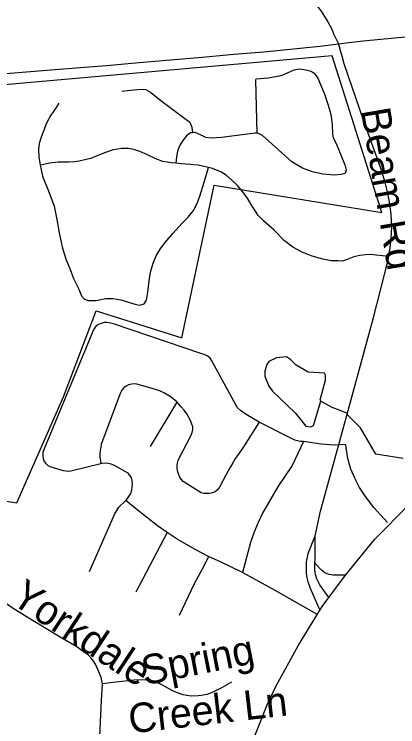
# Model space of a CAD drawing. Extents: x 1383679 to 1536984, y 460658 to 651027.
# Drawn here: x 1424801 to 1426040, y 517873 to 520172 of the extents above; entities that cross this region are included whole.
import ezdxf

# ---------------------------------------------------------------- set-up
doc = ezdxf.new("R2010")
doc.units = 0
for name, color, linetype in [('Default', 7, 'Continuous'), ('Exist Boundary Political City Limit New', 7, 'Continuous'), ('Exist Hydrographic Misc Water Feature', 7, 'Continuous'), ('Exist Road Non-System Type 51', 7, 'Continuous'), ('Exist Road Non-System Type 51 Label', 7, 'Continuous'), ('Exist Road Primary NC UnDivided 4 Lane Attributed', 7, 'Continuous'), ('Exist Road Secondary Type 51 Attributed', 7, 'Continuous'), ('Map Preparation Boundary City Limit Buffer Line', 7, 'Continuous')]:
    doc.layers.add(name, color=color, linetype=linetype)

msp = doc.modelspace()

# ---------------------------------------------------------------- linework, layer by layer
at = {"layer": 'Default'}
msp.add_lwpolyline([(1422823.6, 517723.8), (1422904, 517956.5), (1422867.1, 518120.3), (1422785.2, 518338.7), (1422874.1, 518503.7), (1422925.1, 518771.5), (1423065.2, 518770.9), (1423478.6, 518764.2), (1423776.6, 518761.8), (1424809.6, 518595.3), (1424959.4, 518937.5), (1425065.6, 519215.2), (1425341.9, 519127.2), (1425446.9, 519620.5), (1425988, 519531.9), (1425828.1, 520037.6), (1424757.9, 519942.8), (1424674.9, 520412.2), (1424293.4, 521236.2), (1424534, 521348.2), (1424715.6, 521432.8), (1424890.4, 521491.6), (1424961, 521509.3), (1424693.6, 522254.9)], dxfattribs=at)
at = {"layer": 'Exist Boundary Political City Limit New'}
msp.add_lwpolyline([(1422823.6, 517723.8), (1422904, 517956.5), (1422867.1, 518120.3), (1422785.2, 518338.7), (1422874.1, 518503.7), (1422925.1, 518771.5), (1423065.2, 518770.9), (1423478.6, 518764.2), (1423776.6, 518761.8), (1424809.6, 518595.3), (1424959.4, 518937.5), (1425065.6, 519215.2), (1425341.9, 519127.2), (1425446.9, 519620.5), (1425988, 519531.9), (1425828.1, 520037.6), (1424757.9, 519942.8), (1424674.9, 520412.2), (1424293.4, 521236.2), (1424534, 521348.2), (1424715.6, 521432.8), (1424890.4, 521491.6), (1424961, 521509.3), (1424693.6, 522254.9)], dxfattribs=at)
at = {"layer": 'Exist Hydrographic Misc Water Feature'}
for points in [[(1425790.7, 518922.8), (1425788.7, 518927.9), (1425806.1, 518991.5), (1425806.4, 519007.5), (1425802.6, 519013.6), (1425750.6, 519016.7), (1425711.1, 519039.6), (1425693.5, 519058), (1425679.7, 519066.3), (1425647.6, 519063), (1425623.4, 519051.6), (1425617.1, 519041.7), (1425610.7, 519019.9), (1425610.3, 519003.9), (1425623.6, 518971.6), (1425635.3, 518955.3), (1425707.8, 518885.7), (1425742.8, 518843), (1425758.8, 518840.6), (1425766.9, 518844.4), (1425790.7, 518922.8)], [(1426056.7, 518738), (1425968.9, 518751.9), (1425919.4, 518837.3), (1425877.4, 518878.6), (1425875.8, 518884), (1425828.1, 518903.1), (1425790.7, 518922.8)]]:
    msp.add_lwpolyline(points, dxfattribs=at)
at = {"layer": 'Exist Road Non-System Type 51'}
for p, q in [((1425240.9, 518776.6), (1425326.8, 518919.8)), ((1425294.2, 518499.1), (1425194, 518306.8))]:
    msp.add_line(p, q, dxfattribs=at)
for points in [[(1425772.6, 518488.7), (1425790.2, 518568), (1425876, 518881.1), (1425960.6, 519189.2), (1426008.3, 519378.3), (1426014.6, 519419.1), (1426018.3, 519448.3), (1426020.2, 519486.4), (1426018.4, 519526.8), (1426012.5, 519567), (1426006.3, 519599), (1425997.7, 519632.7), (1425982.5, 519680.2), (1425930.4, 519826.3), (1425866.8, 520012.2), (1425860.1, 520036.6), (1425855.9, 520050.3), (1425851.1, 520066.9), (1425848.4, 520076.7)], [(1425585.9, 519787.6), (1425581.1, 519959.5), (1425582.2, 519963.4), (1425621.1, 519967.1), (1425657.9, 519972.8), (1425671.6, 519977.2), (1425685.4, 519984.3), (1425704.9, 519993), (1425722.1, 519995.9), (1425742.2, 519993), (1425759.6, 519987.9), (1425769.6, 519982.2), (1425781.9, 519965.6), (1425801.4, 519917.3), (1425815.1, 519878.4), (1425823, 519848.2), (1425827.4, 519817.2), (1425828.8, 519785.4), (1425830.9, 519773.2), (1425841, 519755.2), (1425869.1, 519686), (1425873.4, 519668.7), (1425869.9, 519657.8), (1425856.9, 519654.2), (1425834.5, 519652.1), (1425797.1, 519655.7), (1425763.9, 519662.9), (1425731.5, 519675.2), (1425697.6, 519696.1), (1425654.4, 519734.2), (1425603.1, 519780.4), (1425594.5, 519785.4), (1425585.9, 519787.6)], [(1425148.4, 519923.8), (1425186.6, 519928.2), (1425210.4, 519929.6), (1425225.5, 519928.8), (1425240.6, 519920.2), (1425274.5, 519893.5), (1425351.6, 519835.2), (1425368.2, 519823.6), (1425374, 519807.8), (1425376.5, 519789.7)], [(1424945.1, 519884.9), (1424933.6, 519867.6), (1424918.5, 519846), (1424904.8, 519820.8), (1424896.1, 519797.7), (1424888.1, 519775.3), (1424881, 519754.4), (1424879.6, 519735), (1424880.2, 519711.9), (1424884.6, 519684.9)], [(1425376.5, 519789.7), (1425369.6, 519789), (1425357.4, 519779.7), (1425345.1, 519764.5), (1425334.4, 519747.2), (1425327.9, 519729.9), (1425325, 519711.9), (1425322.6, 519691)], [(1425585.9, 519787.6), (1425578.6, 519788.3), (1425469.9, 519773.9), (1425437.4, 519771.8), (1425419.4, 519773.9), (1425402.9, 519783.2), (1425385.5, 519790.5), (1425376.5, 519789.7)], [(1425322.6, 519691), (1425309.2, 519692.2), (1425280.9, 519696.3), (1425257.6, 519705), (1425231.5, 519718.2), (1425206.9, 519728.8), (1425186.8, 519735.2), (1425168.9, 519738.4), (1425148.8, 519738.4), (1425120.4, 519733.8), (1425092.6, 519724.2), (1425062.9, 519712.8), (1425046.9, 519706.8), (1425028.6, 519701.8), (1425010.8, 519697.7), (1424995.6, 519695.4), (1424977.4, 519694), (1424942.1, 519694), (1424915.6, 519691.3), (1424884.6, 519684.9)], [(1425427.9, 519677.6), (1425394.4, 519685.3), (1425369.6, 519687.2), (1425339.9, 519689.5), (1425322.6, 519691)], [(1424884.6, 519684.9), (1424885.4, 519680.2), (1424892.5, 519649.2), (1424912.6, 519598.8), (1424929.2, 519552.7), (1424938.6, 519509.4), (1424945.9, 519466.2), (1424955.2, 519420.8), (1424967.5, 519381.8), (1424979.8, 519351.5), (1424992.6, 519319.1), (1425009.2, 519285.2), (1425017.9, 519262.9), (1425027.4, 519252.1), (1425041, 519248.5), (1425065.5, 519248.5), (1425096.5, 519255), (1425120.2, 519254.2), (1425144.8, 519250.7), (1425194.5, 519234.8), (1425206.8, 519233.3), (1425220.4, 519237.7), (1425227.6, 519249.2), (1425232.8, 519275.2), (1425236.4, 519311.2), (1425240.6, 519340), (1425249.2, 519368.8), (1425259.4, 519392.6), (1425272.4, 519414.2), (1425287.5, 519433.7), (1425313.4, 519464.7), (1425343, 519497.2), (1425363.1, 519517.3), (1425379.8, 519538.2), (1425392, 519561.2), (1425400.6, 519585.1), (1425414.4, 519629.8), (1425427.9, 519677.6)], [(1425527.1, 519613.2), (1425522.4, 519619.1), (1425504, 519636.9), (1425485.8, 519652.4), (1425468.4, 519662.9), (1425437.8, 519675.2), (1425427.9, 519677.6)], [(1426010.1, 519390.2), (1425950.6, 519396.4), (1425935.1, 519395.5), (1425916.9, 519393.7), (1425897.6, 519388.7), (1425876.6, 519380.8), (1425861.1, 519375.4), (1425846.9, 519375.8), (1425824.9, 519376.3), (1425798, 519381.3), (1425762.8, 519391.4), (1425730.8, 519403.8), (1425700.6, 519420.7), (1425674.1, 519440.8), (1425639.4, 519476), (1425606, 519505.7), (1425589.1, 519522.2), (1425581.8, 519533.6), (1425569.4, 519552.8), (1425555.6, 519576.5), (1425539.2, 519598.9), (1425527.1, 519613.2)], [(1425592.4, 518855.1), (1425550.4, 518880.1), (1425531.6, 518892.6), (1425522.1, 518901.8), (1425516.6, 518911.2), (1425446.8, 519039.8), (1425438.8, 519053.9), (1425433.1, 519061.6), (1425425.9, 519068.4), (1425413.9, 519073.6), (1425403.4, 519077.6), (1425124.9, 519171.9), (1425107.6, 519176.3), (1425098.9, 519177.1), (1425092, 519176.8), (1425084.6, 519175.2), (1425078.1, 519173.2), (1425072.4, 519170.8), (1425066.6, 519167.2), (1425062.1, 519162.2), (1425058.6, 519156.6), (1425054.9, 519149), (1425051.6, 519140.9), (1424897.1, 518769.8), (1424893.6, 518757.8), (1424892.6, 518748.3), (1424894.1, 518738.2), (1424897.6, 518728.8), (1424902.6, 518721.8), (1424908.6, 518716.2), (1424915.6, 518712.2), (1424959.2, 518699.7), (1424967.9, 518698.2), (1424975.4, 518697.7), (1424983.4, 518698.7), (1424992.4, 518700.2), (1425080.1, 518722.1)], [(1425326.8, 518919.8), (1425325.9, 518920.7), (1425307.9, 518936), (1425286.4, 518949), (1425273.4, 518955.5), (1425257.1, 518961.1), (1425200.9, 518976.9), (1425189.8, 518978.8), (1425180.4, 518978.2), (1425169.8, 518975.5), (1425161.9, 518971.8), (1425154.4, 518966.7), (1425148.4, 518959.2), (1425142.4, 518948.1), (1425085.6, 518795.6), (1425081.9, 518784.4), (1425080, 518774.2), (1425078.6, 518764.9), (1425077.6, 518754.2), (1425077.6, 518743.5), (1425080.1, 518722.1)], [(1425592.4, 518855.1), (1425541.8, 518775.8), (1425526.8, 518755.6), (1425515.6, 518738.8), (1425507.2, 518724.4), (1425498.9, 518711), (1425490.5, 518696.6), (1425484, 518684.9), (1425463.6, 518645.9), (1425457.5, 518637.5), (1425449.6, 518631), (1425440.8, 518627.2), (1425432.9, 518625.4), (1425424, 518625), (1425413.4, 518625.4), (1425405, 518627.8), (1425395.6, 518632.4), (1425346.9, 518663.6), (1425340.4, 518671), (1425334.4, 518679.8), (1425331.1, 518688.7), (1425328.2, 518697.9), (1425327.4, 518707.2), (1425327.4, 518715.2), (1425328.2, 518723.5), (1425330.1, 518731.4), (1425333.4, 518739.8), (1425371.5, 518811.4), (1425375.6, 518822.1), (1425377.1, 518831.3), (1425377.1, 518840.2), (1425374.8, 518849.5), (1425370.6, 518860.7), (1425358, 518882.1), (1425349.6, 518894.2), (1425340.4, 518905.2), (1425326.8, 518919.8)], [(1425735.1, 518792.8), (1425724.8, 518793.3), (1425707.2, 518797.1), (1425685.4, 518807.8), (1425592.4, 518855.1)], [(1425735.1, 518792.8), (1425698.6, 518715.3), (1425675.4, 518682.2), (1425652.9, 518648.5), (1425604.2, 518563.7), (1425588.4, 518531.4), (1425575.1, 518498.2), (1425564.4, 518467.6), (1425538.4, 518369.8)], [(1425871.8, 518783.3), (1425834.5, 518780.8), (1425792.2, 518784.2), (1425735.1, 518792.8)], [(1426006.9, 518532.2), (1425962.1, 518580.3), (1425935.6, 518615.1), (1425916.5, 518644.9), (1425901.6, 518672.2), (1425887.5, 518703.8), (1425878.4, 518738.6), (1425872.6, 518772.6), (1425871.8, 518783.3)], [(1425080.1, 518722.1), (1425084.6, 518723.2), (1425094.2, 518724.2), (1425103.8, 518723.2), (1425113.2, 518720.8), (1425123.4, 518717.2), (1425165.9, 518692.6), (1425173, 518684.6), (1425178, 518676.1), (1425180.5, 518667.1), (1425181.5, 518657), (1425181, 518647), (1425179, 518635.9), (1425176, 518624.9), (1425161.6, 518602.7)], [(1425044, 518374), (1425125.1, 518557.1), (1425138.5, 518581.2), (1425161.6, 518602.7)], [(1425294.2, 518499.1), (1425263.6, 518520.7), (1425192.4, 518577), (1425161.6, 518602.7)], [(1425428.5, 518422.1), (1425385.4, 518444.5), (1425326.6, 518477.6), (1425294.2, 518499.1)], [(1425788.3, 518249.4), (1425757.7, 518319.1), (1425750, 518340.4), (1425748, 518348.8), (1425747, 518354.6), (1425746.3, 518360.1), (1425745.2, 518367.8), (1425744.6, 518377.9), (1425744.5, 518384.8), (1425744.6, 518392.2), (1425745.3, 518402.2), (1425746, 518411.1), (1425746.6, 518414.8), (1425748.8, 518425), (1425749.6, 518428.4), (1425750.4, 518431.3), (1425772.6, 518488.5), (1425772.6, 518488.7)], [(1425771.9, 518400.5), (1425772.3, 518413.1), (1425773, 518432.1), (1425772.6, 518488.7)], [(1425428.5, 518422.1), (1425412.8, 518390.6), (1425382.1, 518333.4), (1425333.1, 518231.5)], [(1425538.4, 518369.8), (1425469.4, 518403.8), (1425428.5, 518422.1)], [(1425816.7, 518289.7), (1425787.9, 518330.4), (1425778.6, 518349.8), (1425777.1, 518353.4), (1425775.1, 518360.5), (1425773, 518369), (1425772.4, 518372.6), (1425771.9, 518376.1), (1425771.4, 518382.5), (1425771.5, 518387.2), (1425771.5, 518390.3), (1425771.9, 518400.5)], [(1425870.7, 518361.5), (1425835.9, 518361.8), (1425831, 518361.7), (1425824.9, 518362.3), (1425818.1, 518363.7), (1425811.9, 518365.6), (1425807.2, 518367.9), (1425802.8, 518370.4), (1425797.1, 518374.2), (1425794.3, 518376.6), (1425771.9, 518400.5)], [(1425778.1, 518235.8), (1425643.1, 518311.8), (1425538.4, 518369.8)], [(1425085.6, 518010.6), (1425081.5, 518031.8), (1425072.2, 518054.9), (1425066.4, 518067.1), (1425063.9, 518072.7), (1425057.9, 518083), (1425049.7, 518094.3), (1425040.6, 518103.5), (1425028.2, 518112.5), (1425002.4, 518130.1), (1424949.6, 518161.6), (1424837.3, 518229.3), (1424797.3, 518253.7), (1424783, 518263.3), (1424772.5, 518271.7), (1424763.8, 518278.9), (1424757.9, 518285), (1424752.1, 518292.5), (1424746.4, 518301.6), (1424742.1, 518308.9), (1424737.6, 518317.1)], [(1425503, 518016.7), (1425464.7, 517994.5), (1425432.5, 517980), (1425422.8, 517976.9), (1425404.2, 517973.9), (1425395, 517972.6), (1425372, 517971.7), (1425357.9, 517973.4), (1425346.4, 517975.4), (1425333.4, 517979.7), (1425319.9, 517985.6), (1425309, 517990.9), (1425299.5, 517996), (1425289.6, 518001.6), (1425277.9, 518007.8), (1425268.7, 518012.3), (1425260.2, 518015.5), (1425248.8, 518019.4), (1425239.2, 518022.3), (1425227.2, 518023.2), (1425216.2, 518023.5), (1425188.6, 518023), (1425119.1, 518015.5), (1425085.6, 518010.6)], [(1425080.1, 517733.5), (1425075.9, 517756.5), (1425075.3, 517761.1), (1425075.2, 517765.2), (1425075.3, 517768.6), (1425075.3, 517771.8), (1425075.6, 517796), (1425082.4, 517956.8), (1425085.6, 518010.6)]]:
    msp.add_lwpolyline(points, dxfattribs=at)
at = {"layer": 'Exist Road Primary NC UnDivided 4 Lane Attributed'}
msp.add_lwpolyline([(1424263.4, 514052.6), (1424778.9, 515521.9), (1424831.4, 515666.8), (1424961.1, 516037.5), (1425008, 516184.9), (1425129.2, 516542.7), (1425182.9, 516714.4), (1425232.8, 516866.3), (1425354.5, 517247.1), (1425456.4, 517534.2), (1425548.8, 517765.4), (1425582.2, 517853.9), (1425618.1, 517943), (1425647.3, 518004.2), (1425719, 518136.2), (1425795.6, 518261), (1425870.7, 518361.5), (1425965.6, 518478), (1426075, 518589.2), (1426252.1, 518737.8), (1427466.3, 519638.3)], dxfattribs=at)
at = {"layer": 'Exist Road Secondary Type 51 Attributed'}
for points in [[(1424585, 522483.9), (1424843.2, 521739.4), (1424906.1, 521554.9), (1424943, 521439.9), (1424962.5, 521381.3), (1425001.5, 521285.8), (1425042.8, 521192.5), (1425092.7, 521101.3), (1425216.3, 520934.2), (1425422.4, 520671.5), (1425594.9, 520442.6), (1425686, 520325.3), (1425749, 520236.4), (1425792.3, 520182.1), (1425814, 520147.4), (1425827.1, 520123.5), (1425833.6, 520106.1), (1425848.4, 520076.7)], [(1425848.4, 520076.7), (1425889.9, 520081.7), (1425928.2, 520086), (1426075, 520100.5)], [(1424680.8, 519972.7), (1424919.1, 519992.8), (1425014.5, 520000), (1425098.4, 520006.6), (1425204.4, 520016.2), (1425305.4, 520025.1), (1425407.7, 520033.8), (1425509.6, 520042.6), (1425607.2, 520051.1), (1425787.9, 520069), (1425848.4, 520076.7)]]:
    msp.add_lwpolyline(points, dxfattribs=at)
at = {"layer": 'Map Preparation Boundary City Limit Buffer Line'}
msp.add_lwpolyline([(1422823.6, 517723.8), (1422904, 517956.5), (1422867.1, 518120.3), (1422785.2, 518338.7), (1422874.1, 518503.7), (1422925.1, 518771.5), (1423065.2, 518770.9), (1423478.6, 518764.2), (1423776.6, 518761.8), (1424809.6, 518595.3), (1424959.4, 518937.5), (1425065.6, 519215.2), (1425341.9, 519127.2), (1425446.9, 519620.5), (1425988, 519531.9), (1425828.1, 520037.6), (1424757.9, 519942.8), (1424674.9, 520412.2), (1424293.4, 521236.2), (1424534, 521348.2), (1424715.6, 521432.8), (1424890.4, 521491.6), (1424961, 521509.3), (1424693.6, 522254.9)], dxfattribs=at)
msp.add_lwpolyline([(1422823.6, 517723.8), (1422904, 517956.5), (1422867.1, 518120.3), (1422785.2, 518338.7), (1422874.1, 518503.7), (1422925.1, 518771.5), (1423065.2, 518770.9), (1423478.6, 518764.2), (1423776.6, 518761.8), (1424809.6, 518595.3), (1424959.4, 518937.5), (1425065.6, 519215.2), (1425341.9, 519127.2), (1425446.9, 519620.5), (1425988, 519531.9), (1425828.1, 520037.6), (1424757.9, 519942.8), (1424674.9, 520412.2), (1424293.4, 521236.2), (1424534, 521348.2), (1424715.6, 521432.8), (1424890.4, 521491.6), (1424961, 521509.3), (1424693.6, 522254.9)], dxfattribs=at)

# ---------------------------------------------------------------- texts
at = {"layer": 'Exist Road Non-System Type 51 Label'}
for s, rotation, p in [('Beam Rd', 279.6204, (1425919.8, 519862.6)), ('Yorkdale', 326.542, (1424785.2, 518274.3)), ('Spring', 11.2595, (1425222.1, 518006.2)), ('Creek Ln', 6.5606, (1425175.3, 517850.5))]:
    msp.add_text(s, height=95, rotation=rotation, dxfattribs=at).set_placement(p)

doc.saveas('drawing.dxf')
